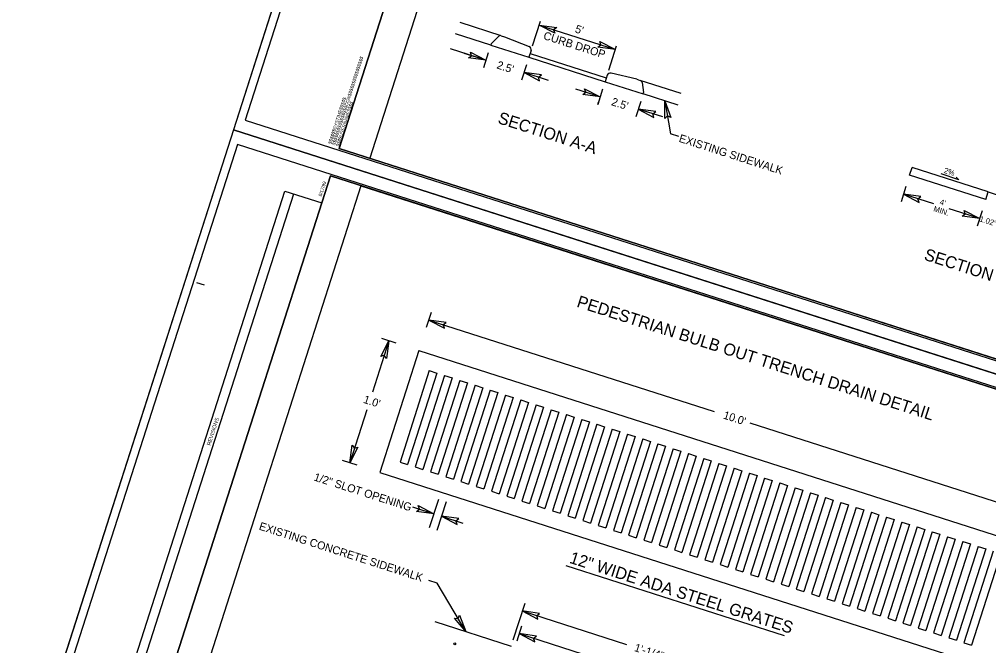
# Model space of a CAD drawing. Extents: x 928111 to 937215, y 684320 to 686530.
# Drawn here: x 933597.6 to 933658.2, y 684635.2 to 684674.3 of the extents above; entities that cross this region are included whole.
import ezdxf

# ---------------------------------------------------------------- set-up
doc = ezdxf.new("R2010")
doc.units = 0
for name, color, linetype in [('Default', 7, 'Continuous'), ('Exist Roads EOP', 7, 'Continuous'), ('Prop Conc 5in Monolithic Keyed In Island', 7, 'Continuous'), ('Prop Dimension', 7, 'Continuous'), ('Prop DSN Text', 7, 'Continuous'), ('Prop Terminator CELL', 7, 'Continuous'), ('Sheet Block Revision CELL', 7, 'Continuous'), ('Sheet Clip Boundary CELL', 7, 'Continuous'), ('Sheet Cutting Line CELL', 7, 'Continuous'), ('Sheet Layout Plan Border', 7, 'Continuous'), ('Sheet Plan CELL', 7, 'Continuous'), ('Sheet Plan Layout CELL', 7, 'Continuous'), ('Sheet Plot Border Inside CELL', 7, 'Continuous'), ('Sheet Plot Border Outside CELL', 7, 'Continuous'), ('Typical Arrow Superelevation CELL', 7, 'Continuous')]:
    doc.layers.add(name, color=color, linetype=linetype)

# ---------------------------------------------------------------- blocks, each defined once
blk = doc.blocks.new('SUPER SLOPE ARROW RIGHT')
at = {"layer": 'Typical Arrow Superelevation CELL'}
for q in [(0.08, 0.09), (3.95, 0.47)]:
    blk.add_line((4.74, 0), q, dxfattribs=at)

msp = doc.modelspace()

# ---------------------------------------------------------------- linework, layer by layer
at = {"layer": 'Default'}
msp.add_circle((933624.813, 684635.287), 0.0566, dxfattribs=at)
at = {"layer": 'Exist Roads EOP'}
for p, q in [((933627.709, 684673.284), (933625.151, 684674.104)), ((933627.064, 684672.703), (933624.859, 684673.41)), ((933638.958, 684669.678), (933636.399, 684670.498)), ((933638.761, 684668.954), (933636.587, 684669.651)), ((933623.567, 684636.672), (933628.328, 684635.146))]:
    msp.add_line(p, q, dxfattribs=at)
at = {"layer": 'Prop Conc 5in Monolithic Keyed In Island'}
for p, q in [((933627.089, 684672.782), (933627.539, 684673.242)), ((933627.709, 684673.284), (933627.928, 684673.214)), ((933627.928, 684673.214), (933629.462, 684672.604)), ((933627.089, 684672.782), (933627.064, 684672.703)), ((933627.064, 684672.703), (933629.445, 684671.94)), ((933629.579, 684672.357), (933629.445, 684671.94)), ((933629.521, 684672.178), (933634.282, 684670.652)), ((933629.445, 684671.94), (933634.206, 684670.414)), ((933634.336, 684670.819), (933634.206, 684670.414)), ((933636.181, 684670.569), (933634.587, 684670.948)), ((933634.206, 684670.414), (933636.587, 684669.651)), ((933636.181, 684670.569), (933636.399, 684670.498)), ((933636.514, 684670.365), (933636.612, 684669.73)), ((933636.587, 684669.651), (933636.612, 684669.73)), ((933653.23, 684664.578), (933653.383, 684665.055)), ((933658.144, 684663.528), (933653.383, 684665.055)), ((933657.992, 684663.052), (933653.23, 684664.578)), ((933618.954, 684663.916), (933665.073, 684649.133)), ((933657.992, 684663.052), (933658.144, 684663.528)), ((933658.144, 684663.528), (933659.096, 684663.223)), ((933622.578, 684653.617), (933620.136, 684645.999)), ((933622.578, 684653.617), (933660.669, 684641.408)), ((933620.136, 684645.999), (933658.227, 684633.789))]:
    msp.add_line(p, q, dxfattribs=at)
for centre, radius, start, end in [((933627.658, 684673.125), 0.167, 72.22734, 135.61762), ((933629.388, 684672.418), 0.2, 342.22734, 68.32614), ((933634.526, 684670.757), 0.2, 72.22734, 162.22734), ((933636.349, 684670.339), 0.167, 8.83706, 72.22734)]:
    msp.add_arc(centre, radius, start, end, dxfattribs=at)
at = {"layer": 'Prop Dimension'}
for p, q in [((933629.674, 684672.654), (933630.166, 684674.189)), ((933630.089, 684673.951), (933634.851, 684672.424)), ((933634.435, 684671.128), (933634.927, 684672.662)), ((933626.759, 684671.751), (933624.554, 684672.458)), ((933626.759, 684671.751), (933625.4, 684672.187)), ((933626.911, 684672.227), (933626.606, 684671.275)), ((933629.292, 684671.464), (933628.987, 684670.512)), ((933630.667, 684670.498), (933629.14, 684670.988)), ((933633.901, 684669.462), (933632.374, 684669.951)), ((933634.054, 684669.938), (933633.748, 684668.985)), ((933633.748, 684668.985), (933633.795, 684669.131)), ((933636.434, 684669.175), (933636.129, 684668.222)), ((933637.945, 684669.215), (933638.282, 684667.164)), ((933637.809, 684668.209), (933636.282, 684668.698)), ((933653.001, 684663.864), (933652.696, 684662.912)), ((933654.737, 684662.783), (933652.849, 684663.388)), ((933657.61, 684661.862), (933655.7, 684662.474)), ((933657.763, 684662.338), (933657.457, 684661.386)), ((933623.341, 684655.998), (933623.035, 684655.046)), ((933623.188, 684655.522), (933641.013, 684649.808)), ((933620.699, 684654.219), (933619.672, 684651.014)), ((933621.149, 684654.075), (933620.249, 684654.363)), ((933623.225, 684652.36), (933621.393, 684646.646)), ((933623.701, 684652.207), (933621.869, 684646.493)), ((933624.177, 684652.054), (933622.345, 684646.341)), ((933623.225, 684652.36), (933623.701, 684652.207)), ((933624.177, 684652.054), (933624.653, 684651.902)), ((933624.653, 684651.902), (933622.822, 684646.188)), ((933625.129, 684651.749), (933623.298, 684646.036)), ((933625.605, 684651.597), (933623.774, 684645.883)), ((933626.081, 684651.444), (933624.25, 684645.73)), ((933625.129, 684651.749), (933625.605, 684651.597)), ((933626.081, 684651.444), (933626.558, 684651.291)), ((933626.558, 684651.291), (933624.726, 684645.578)), ((933627.034, 684651.139), (933625.202, 684645.425)), ((933627.51, 684650.986), (933625.678, 684645.272)), ((933627.986, 684650.833), (933626.155, 684645.12)), ((933627.034, 684651.139), (933627.51, 684650.986)), ((933627.986, 684650.833), (933628.462, 684650.681)), ((933628.462, 684650.681), (933626.631, 684644.967)), ((933628.938, 684650.528), (933627.107, 684644.815)), ((933629.414, 684650.376), (933627.583, 684644.662)), ((933629.891, 684650.223), (933628.059, 684644.509)), ((933628.938, 684650.528), (933629.414, 684650.376)), ((933629.891, 684650.223), (933630.367, 684650.07)), ((933619.315, 684649.901), (933618.257, 684646.601)), ((933630.367, 684650.07), (933628.535, 684644.357)), ((933630.843, 684649.918), (933629.011, 684644.204)), ((933631.319, 684649.765), (933629.488, 684644.051)), ((933631.795, 684649.613), (933629.964, 684643.899)), ((933630.843, 684649.918), (933631.319, 684649.765)), ((933631.795, 684649.613), (933632.271, 684649.46)), ((933632.271, 684649.46), (933630.44, 684643.746)), ((933632.747, 684649.307), (933630.916, 684643.594)), ((933633.224, 684649.155), (933631.392, 684643.441)), ((933633.7, 684649.002), (933631.868, 684643.288)), ((933632.747, 684649.307), (933633.224, 684649.155)), ((933633.7, 684649.002), (933634.176, 684648.849)), ((933643.24, 684649.094), (933661.279, 684643.312)), ((933634.176, 684648.849), (933632.344, 684643.136)), ((933634.652, 684648.697), (933632.821, 684642.983)), ((933635.128, 684648.544), (933633.297, 684642.831)), ((933635.604, 684648.392), (933633.773, 684642.678)), ((933634.652, 684648.697), (933635.128, 684648.544)), ((933635.604, 684648.392), (933636.08, 684648.239)), ((933636.08, 684648.239), (933634.249, 684642.525)), ((933636.557, 684648.086), (933634.725, 684642.373)), ((933637.033, 684647.934), (933635.201, 684642.22)), ((933637.509, 684647.781), (933635.677, 684642.067)), ((933636.557, 684648.086), (933637.033, 684647.934)), ((933637.509, 684647.781), (933637.985, 684647.628)), ((933637.985, 684647.628), (933636.153, 684641.915)), ((933638.461, 684647.476), (933636.63, 684641.762)), ((933638.937, 684647.323), (933637.106, 684641.61)), ((933639.413, 684647.171), (933637.582, 684641.457)), ((933638.461, 684647.476), (933638.937, 684647.323)), ((933639.413, 684647.171), (933639.889, 684647.018)), ((933618.707, 684646.457), (933617.808, 684646.745)), ((933621.393, 684646.646), (933621.869, 684646.493)), ((933639.889, 684647.018), (933638.058, 684641.304)), ((933640.366, 684646.865), (933638.534, 684641.152)), ((933640.842, 684646.713), (933639.01, 684640.999)), ((933641.318, 684646.56), (933639.486, 684640.846)), ((933640.366, 684646.865), (933640.842, 684646.713)), ((933641.318, 684646.56), (933641.794, 684646.407)), ((933622.345, 684646.341), (933622.822, 684646.188)), ((933623.298, 684646.036), (933623.774, 684645.883)), ((933641.794, 684646.407), (933639.963, 684640.694)), ((933642.27, 684646.255), (933640.439, 684640.541)), ((933642.746, 684646.102), (933640.915, 684640.389)), ((933642.27, 684646.255), (933642.746, 684646.102)), ((933624.25, 684645.73), (933624.726, 684645.578)), ((933625.202, 684645.425), (933625.678, 684645.272)), ((933643.222, 684645.95), (933641.391, 684640.236)), ((933643.699, 684645.797), (933641.867, 684640.083)), ((933644.175, 684645.644), (933642.343, 684639.931)), ((933644.651, 684645.492), (933642.819, 684639.778)), ((933643.222, 684645.95), (933643.699, 684645.797)), ((933644.175, 684645.644), (933644.651, 684645.492)), ((933626.155, 684645.12), (933626.631, 684644.967)), ((933627.107, 684644.815), (933627.583, 684644.662)), ((933645.127, 684645.339), (933643.296, 684639.625)), ((933645.603, 684645.187), (933643.772, 684639.473)), ((933646.079, 684645.034), (933644.248, 684639.32)), ((933646.555, 684644.881), (933644.724, 684639.168)), ((933645.127, 684645.339), (933645.603, 684645.187)), ((933646.079, 684645.034), (933646.555, 684644.881)), ((933623.792, 684644.302), (933623.223, 684642.525)), ((933623.792, 684644.302), (933623.223, 684642.525)), ((933624.268, 684644.149), (933623.699, 684642.372)), ((933628.059, 684644.509), (933628.535, 684644.357)), ((933629.011, 684644.204), (933629.488, 684644.051)), ((933647.032, 684644.729), (933645.2, 684639.015)), ((933647.508, 684644.576), (933645.676, 684638.862)), ((933647.984, 684644.423), (933646.152, 684638.71)), ((933648.46, 684644.271), (933646.629, 684638.557)), ((933647.032, 684644.729), (933647.508, 684644.576)), ((933647.984, 684644.423), (933648.46, 684644.271)), ((933622.17, 684643.842), (933623.507, 684643.413)), ((933629.964, 684643.899), (933630.44, 684643.746)), ((933630.916, 684643.594), (933631.392, 684643.441)), ((933648.936, 684644.118), (933647.105, 684638.405)), ((933649.412, 684643.966), (933647.581, 684638.252)), ((933649.888, 684643.813), (933648.057, 684638.099)), ((933650.364, 684643.66), (933648.533, 684637.947)), ((933648.936, 684644.118), (933649.412, 684643.966)), ((933649.888, 684643.813), (933650.364, 684643.66)), ((933623.984, 684643.261), (933625.321, 684642.832)), ((933631.868, 684643.288), (933632.344, 684643.136)), ((933632.821, 684642.983), (933633.297, 684642.831)), ((933650.841, 684643.508), (933649.009, 684637.794)), ((933651.317, 684643.355), (933649.485, 684637.641)), ((933651.793, 684643.202), (933649.961, 684637.489)), ((933652.269, 684643.05), (933650.438, 684637.336)), ((933650.841, 684643.508), (933651.317, 684643.355)), ((933651.793, 684643.202), (933652.269, 684643.05)), ((933633.773, 684642.678), (933634.249, 684642.525)), ((933634.725, 684642.373), (933635.201, 684642.22)), ((933652.745, 684642.897), (933650.914, 684637.184)), ((933653.221, 684642.745), (933651.39, 684637.031)), ((933653.697, 684642.592), (933651.866, 684636.878)), ((933654.174, 684642.439), (933652.342, 684636.726)), ((933652.745, 684642.897), (933653.221, 684642.745)), ((933653.697, 684642.592), (933654.174, 684642.439)), ((933635.677, 684642.067), (933636.153, 684641.915)), ((933636.63, 684641.762), (933637.106, 684641.61)), ((933654.65, 684642.287), (933652.818, 684636.573)), ((933655.126, 684642.134), (933653.294, 684636.42)), ((933655.602, 684641.981), (933653.771, 684636.268)), ((933656.078, 684641.829), (933654.247, 684636.115)), ((933654.65, 684642.287), (933655.126, 684642.134)), ((933655.602, 684641.981), (933656.078, 684641.829)), ((933637.582, 684641.457), (933638.058, 684641.304)), ((933638.534, 684641.152), (933639.01, 684640.999)), ((933656.554, 684641.676), (933654.723, 684635.963)), ((933657.03, 684641.524), (933655.199, 684635.81)), ((933657.507, 684641.371), (933655.675, 684635.657)), ((933657.983, 684641.218), (933656.151, 684635.505)), ((933656.554, 684641.676), (933657.03, 684641.524)), ((933657.507, 684641.371), (933657.983, 684641.218)), ((933639.486, 684640.846), (933639.963, 684640.694)), ((933640.439, 684640.541), (933640.915, 684640.389)), ((933658.459, 684641.066), (933656.627, 684635.352)), ((933658.935, 684640.913), (933657.104, 684635.199)), ((933631.748, 684640.178), (933645.389, 684635.806)), ((933641.391, 684640.236), (933641.867, 684640.083)), ((933642.343, 684639.931), (933642.819, 684639.778)), ((933643.296, 684639.625), (933643.772, 684639.473)), ((933644.248, 684639.32), (933644.724, 684639.168)), ((933625.506, 684636.05), (933623.723, 684639.067)), ((933645.2, 684639.015), (933645.676, 684638.862)), ((933646.152, 684638.71), (933646.629, 684638.557)), ((933647.105, 684638.405), (933647.581, 684638.252)), ((933648.057, 684638.099), (933648.533, 684637.947)), ((933629.184, 684637.814), (933628.449, 684635.522)), ((933649.009, 684637.794), (933649.485, 684637.641)), ((933649.961, 684637.489), (933650.438, 684637.336)), ((933629.031, 684637.338), (933635.54, 684635.252)), ((933650.914, 684637.184), (933651.39, 684637.031)), ((933651.866, 684636.878), (933652.342, 684636.726)), ((933628.992, 684636.398), (933628.687, 684635.445)), ((933652.818, 684636.573), (933653.294, 684636.42)), ((933653.771, 684636.268), (933654.247, 684636.115)), ((933628.84, 684635.922), (933635.744, 684633.709)), ((933654.723, 684635.963), (933655.199, 684635.81)), ((933655.675, 684635.657), (933656.151, 684635.505)), ((933656.627, 684635.352), (933657.104, 684635.199))]:
    msp.add_line(p, q, dxfattribs=at)
at = {"layer": 'Prop DSN Text'}
for p, q in [((933638.812, 684666.994), (933638.282, 684667.164)), ((933623.723, 684639.067), (933623.194, 684639.236))]:
    msp.add_line(p, q, dxfattribs=at)
at = {"layer": 'Prop Terminator CELL'}
for points in [[(933631.061, 684673.444), (933630.089, 684673.951), (933631.182, 684673.802), (933630.992, 684673.661)], [(933633.879, 684672.931), (933634.851, 684672.424), (933633.758, 684672.573), (933633.948, 684672.714)], [(933625.787, 684672.258), (933626.759, 684671.751), (933625.666, 684671.9), (933625.856, 684672.04)], [(933630.225, 684670.835), (933629.14, 684670.988), (933630.115, 684670.473), (933630.042, 684670.698)], [(933632.929, 684669.968), (933633.901, 684669.462), (933632.808, 684669.61), (933632.998, 684669.751)], [(933637.937, 684668.12), (933637.945, 684669.215), (933638.311, 684668.175), (933638.099, 684668.28)], [(933637.367, 684668.546), (933636.282, 684668.698), (933637.257, 684668.184), (933637.184, 684668.409)], [(933653.934, 684663.236), (933652.849, 684663.388), (933653.824, 684662.874), (933653.751, 684663.099)], [(933656.638, 684662.369), (933657.61, 684661.862), (933656.517, 684662.011), (933656.707, 684662.151)], [(933624.273, 684655.369), (933623.188, 684655.522), (933624.164, 684655.007), (933624.091, 684655.232)], [(933620.193, 684653.248), (933620.699, 684654.219), (933620.551, 684653.126), (933620.41, 684653.317)], [(933618.764, 684647.573), (933618.257, 684646.601), (933618.406, 684647.694), (933618.547, 684647.504)], [(933622.536, 684643.92), (933623.507, 684643.413), (933622.415, 684643.562), (933622.605, 684643.703)], [(933625.069, 684643.108), (933623.984, 684643.261), (933624.959, 684642.747), (933624.886, 684642.972)], [(933625.116, 684637.075), (933625.506, 684636.05), (933624.788, 684636.888), (933625.024, 684636.867)], [(933630.116, 684637.186), (933629.031, 684637.338), (933630.007, 684636.824), (933629.934, 684637.049)], [(933629.925, 684635.769), (933628.84, 684635.922), (933629.815, 684635.407), (933629.742, 684635.632)]]:
    msp.add_lwpolyline(points, close=True, dxfattribs=at)
at = {"layer": 'Sheet Block Revision CELL'}
msp.add_line((933605.103, 684633.281), (933614.756, 684663.398), dxfattribs=at)
msp.add_lwpolyline([(933604.549, 684633.458), (933614.202, 684663.575), (933616.509, 684662.837), (933606.855, 684632.72)], close=True, dxfattribs=at)
at = {"layer": 'Sheet Clip Boundary CELL'}
for points in [[(933619.504, 684665.63), (933672.831, 684648.536), (933683.069, 684680.476), (933675.86, 684682.787), (933678.442, 684690.842), (933632.324, 684705.625)], [(933606.134, 684623.92), (933659.462, 684606.826), (933669.7, 684638.766), (933662.491, 684641.077), (933665.073, 684649.133), (933618.954, 684663.916)]]:
    msp.add_lwpolyline(points, close=True, dxfattribs=at)
at = {"layer": 'Sheet Cutting Line CELL'}
for p, q in [((933624.352, 684709.125), (933610.982, 684667.415)), ((933610.982, 684667.415), (933597.613, 684625.706)), ((933610.982, 684667.415), (933675.109, 684646.86)), ((933610.982, 684667.415), (933675.109, 684646.86)), ((933675.109, 684646.86), (933610.982, 684667.415))]:
    msp.add_line(p, q, dxfattribs=at)
at = {"layer": 'Sheet Layout Plan Border'}
for points in [[(933619.504, 684665.63), (933672.831, 684648.536), (933683.069, 684680.476), (933675.86, 684682.787), (933678.442, 684690.842), (933632.324, 684705.625)], [(933606.134, 684623.92), (933659.462, 684606.826), (933669.7, 684638.766), (933662.491, 684641.077), (933665.073, 684649.133), (933618.954, 684663.916)]]:
    msp.add_lwpolyline(points, close=True, dxfattribs=at)
at = {"layer": 'Sheet Plan CELL'}
for p, q in [((933617.599, 684666.24), (933617.599, 684666.24)), ((933617.599, 684666.24), (933617.599, 684666.24)), ((933617.05, 684664.526), (933617.05, 684664.526)), ((933608.676, 684657.863), (933609.153, 684657.711))]:
    msp.add_line(p, q, dxfattribs=at)
for points in [[(933687.557, 684687.921), (933630.419, 684706.236), (933617.599, 684666.24), (933674.736, 684647.926)], [(933617.599, 684666.24), (933630.418, 684706.235), (933679.936, 684690.364), (933678.104, 684684.648), (933685.724, 684682.205), (933674.736, 684647.926)], [(933674.188, 684646.211), (933617.05, 684664.526), (933604.229, 684624.531), (933661.366, 684606.216)], [(933604.229, 684624.531), (933617.048, 684664.525), (933666.567, 684648.654), (933664.735, 684642.938), (933672.354, 684640.495), (933661.366, 684606.216)]]:
    msp.add_lwpolyline(points, close=True, dxfattribs=at)
at = {"layer": 'Sheet Plan Layout CELL'}
for points in [[(933630.418, 684706.235), (933617.599, 684666.24), (933674.736, 684647.926), (933684.973, 684679.865), (933675.86, 684682.787), (933678.442, 684690.842)], [(933617.048, 684664.525), (933604.229, 684624.531), (933661.366, 684606.216), (933671.604, 684638.156), (933662.491, 684641.077), (933665.073, 684649.133)]]:
    msp.add_lwpolyline(points, close=True, dxfattribs=at)
at = {"layer": 'Sheet Plot Border Inside CELL'}
for points in [[(933611.722, 684668.018), (933675.181, 684647.678), (933688.063, 684687.863), (933624.603, 684708.204)], [(933598.352, 684626.309), (933661.812, 684605.968), (933674.693, 684646.154), (933611.233, 684666.495)]]:
    msp.add_lwpolyline(points, close=True, dxfattribs=at)
at = {"layer": 'Sheet Plot Border Outside CELL'}
for points in [[(933610.982, 684667.415), (933675.109, 684646.86), (933688.478, 684688.57), (933624.352, 684709.125)], [(933597.613, 684625.706), (933661.739, 684605.151), (933675.109, 684646.86), (933610.982, 684667.415)]]:
    msp.add_lwpolyline(points, close=True, dxfattribs=at)

# ---------------------------------------------------------------- block references
at = {"layer": 'Prop Conc 5in Monolithic Keyed In Island', "xscale": 0.25, "yscale": 0.25, "rotation": -17.77265933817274}
msp.add_blockref('SUPER SLOPE ARROW RIGHT', (933655.17, 684664.64), dxfattribs=at)

# ---------------------------------------------------------------- texts
at = {"layer": 'Prop DSN Text'}
for s, height, rotation, p in [("5'", 0.5, 342.22734, (933632.288, 684673.505)), ('CURB DROP', 0.5, 342.22734, (933630.307, 684673.09)), ("2.5'", 0.5, 342.22734, (933627.398, 684671.254)), ("2.5'", 0.5, 342.22734, (933634.558, 684668.959)), ('SECTION A-A', 0.75, 342.22734, (933627.45, 684667.836)), ('EXISTING SIDEWALK', 0.5, 342.22734, (933638.777, 684666.668)), ('2%', 0.35, 342.22722, (933655.344, 684664.721)), ("4'", 0.35, 342.22722, (933655.08, 684662.752)), ('MIN.', 0.35, 342.22722, (933654.691, 684662.326)), ('1.02"', 0.35, 342.22722, (933657.567, 684661.698)), ('SECTION B-B', 0.75, 342.22734, (933654.082, 684659.3)), (' PEDESTRIAN BULB OUT TRENCH DRAIN DETAIL', 0.75, 342.22734, (933632.117, 684656.443)), ("1.0'", 0.5, 342.22734, (933619.062, 684650.357)), ("10.0'", 0.5, 342.22734, (933641.544, 684649.375)), ('1/2" SLOT OPENING', 0.5, 342.22734, (933615.968, 684645.506)), ('EXISTING CONCRETE SIDEWALK', 0.5, 342.22734, (933612.543, 684642.432)), ('12" WIDE ADA STEEL GRATES', 0.75, 342.22734, (933631.93, 684640.355)), ('1\'-1/4"', 0.5, 342.22734, (933635.99, 684634.845))]:
    msp.add_text(s, height=height, rotation=rotation, dxfattribs=at).set_placement(p)
at = {"layer": 'Sheet Block Revision CELL'}
msp.add_text('REVISIONS', height=0.24, rotation=72.22734, dxfattribs=at).set_placement((933609.542, 684647.659))
at = {"layer": 'Sheet Plan CELL'}
for s, p in [('$$$$$$$$$$$$$$$$DGN$$$$$$$$$$$$$$$$', (933617.337, 684666.423)), ('$$$$$$SYSTIME$$$$$', (933617.105, 684666.497)), ('$$$$USERNAME$$$$', (933617.587, 684666.344)), ('8/17/99', (933616.497, 684663.224))]:
    msp.add_text(s, height=0.21, rotation=72.22734, dxfattribs=at).set_placement(p)

doc.saveas('drawing.dxf')
